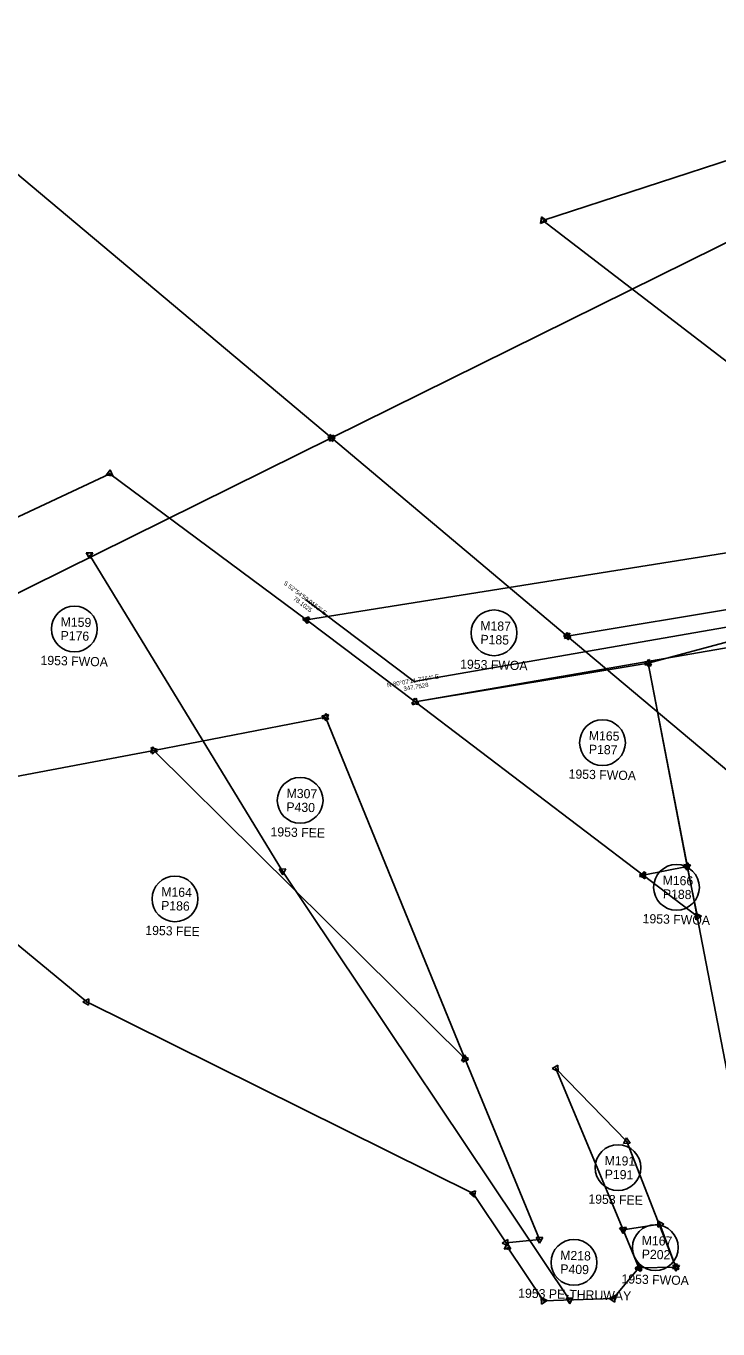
# Model space of a CAD drawing. Extents: x 325029 to 414988, y 1517527 to 1550420.
# Drawn here: x 363499 to 363896, y 1523755 to 1524502 of the extents above; entities that cross this region are included whole.
import ezdxf

# ---------------------------------------------------------------- set-up
doc = ezdxf.new("R2010")
doc.units = 0
for name, color, linetype in [('ADEFAULT', 7, 'Continuous'), ('Level 56', 7, 'Continuous'), ('MEE', 7, 'Continuous'), ('MHB', 7, 'Continuous'), ('MHBWOA', 7, 'Continuous'), ('MRBL1', 7, 'Continuous'), ('MRBL2', 7, 'Continuous'), ('XDEFAULT_P', 7, 'Continuous'), ('XDEFAULT_P_T', 7, 'Continuous')]:
    doc.layers.add(name, color=color, linetype=linetype)

msp = doc.modelspace()

# ---------------------------------------------------------------- linework, layer by layer
at = {"layer": 'ADEFAULT'}
for points in [[(363658.02, 1524161.47), (363661.51, 1524162.93)], [(363661.04, 1524159.19), (363658.02, 1524161.47)], [(363658.15, 1524161.98), (363661.89, 1524162.58)], [(363660.53, 1524159.05), (363658.15, 1524161.98)], [(363661.89, 1524162.58), (363660.53, 1524159.05)], [(363661.51, 1524162.93), (363661.04, 1524159.19)], [(363720.39, 1524113.46), (363722.99, 1524116.19)], [(363722.99, 1524116.19), (363724.06, 1524112.57)], [(363724.06, 1524112.57), (363720.39, 1524113.46)], [(363571.99, 1524084.21), (363571.14, 1524087.89)], [(363571.14, 1524087.89), (363574.75, 1524086.79)], [(363574.75, 1524086.79), (363571.99, 1524084.21)], [(363532.04, 1523942.18), (363535.4, 1523943.9)], [(363535.4, 1523943.9), (363535.21, 1523940.13)], [(363535.21, 1523940.13), (363532.04, 1523942.18)], [(363749.07, 1523908.3), (363750.73, 1523911.69)], [(363752.84, 1523908.55), (363749.07, 1523908.3)], [(363750.73, 1523911.69), (363752.84, 1523908.55)], [(363753.56, 1523832.56), (363757.14, 1523833.77)], [(363756.39, 1523830.07), (363753.56, 1523832.56)], [(363757.14, 1523833.77), (363756.39, 1523830.07)], [(363772.42, 1523803.69), (363775.52, 1523805.84)], [(363775.84, 1523802.08), (363772.42, 1523803.69)], [(363775.52, 1523805.84), (363775.84, 1523802.08)], [(363793.7, 1523803.66), (363791.86, 1523806.96)], [(363791.86, 1523806.96), (363795.64, 1523806.9)], [(363795.64, 1523806.9), (363793.7, 1523803.66)]]:
    msp.add_lwpolyline(points, dxfattribs=at)
for centre, radius in [((363660.19, 1524161.2), 1.09), ((363660.19, 1524161.2), 1.09), ((363722.48, 1524114.08), 0.227), ((363572.62, 1524086.3), 0.227), ((363534.22, 1523942.07), 0.227), ((363750.87, 1523909.51), 0.227), ((363755.7, 1523832.14), 0.227), ((363774.6, 1523803.87), 0.227), ((363793.73, 1523805.84), 0.227)]:
    msp.add_circle(centre, radius, dxfattribs=at)
at = {"layer": 'Level 56'}
for centre in [(363527.12, 1524155.92), (363767.66, 1524153.73), (363829.82, 1524090.72), (363656.53, 1524057.64), (363872.25, 1524007.76), (363584.75, 1524001.12), (363838.73, 1523847.02), (363860.13, 1523801.16), (363813.48, 1523792.66)]:
    msp.add_circle(centre, 13.12, dxfattribs=at)
at = {"layer": 'MEE'}
for p, q in [((363795.93, 1523770.69), (363775.36, 1523801.44)), ((363850.71, 1523789.48), (363835.91, 1523771.88)), ((363835.91, 1523771.88), (363795.93, 1523770.69))]:
    msp.add_line(p, q, dxfattribs=at)
for points in [[(363773.55, 1523800.23), (363775.22, 1523803.62)], [(363775.22, 1523803.62), (363777.32, 1523800.48)], [(363777.32, 1523800.48), (363773.55, 1523800.23)], [(363848.66, 1523788.74), (363851.09, 1523791.63)], [(363852.38, 1523788.08), (363848.66, 1523788.74)], [(363851.09, 1523791.63), (363852.38, 1523788.08)], [(363794.93, 1523768.75), (363794.75, 1523772.52)], [(363794.75, 1523772.52), (363798.11, 1523770.79)], [(363833.74, 1523772.04), (363837.14, 1523773.68)], [(363836.86, 1523769.92), (363833.74, 1523772.04)], [(363837.14, 1523773.68), (363836.86, 1523769.92)], [(363798.11, 1523770.79), (363794.93, 1523768.75)]]:
    msp.add_lwpolyline(points, dxfattribs=at)
for centre, radius in [((363775.36, 1523801.44), 1.09), ((363850.71, 1523789.48), 1.09), ((363835.91, 1523771.88), 0.227), ((363795.93, 1523770.69), 0.227)]:
    msp.add_circle(centre, radius, dxfattribs=at)
at = {"layer": 'MHB'}
for p, q in [((363795.7, 1524390.2), (364079.15, 1524482.56)), ((363937.94, 1524280.97), (363795.7, 1524390.2)), ((363170.57, 1524068.42), (363547.37, 1524244.94)), ((363547.37, 1524244.94), (363660.19, 1524161.2)), ((363671.1, 1524105.36), (363572.62, 1524086.3)), ((363750.87, 1523909.51), (363671.1, 1524105.36)), ((363572.62, 1524086.3), (363399.47, 1524053.32)), ((363572.62, 1524086.3), (363750.87, 1523909.51)), ((363750.87, 1523909.51), (363572.62, 1524086.3)), ((363399.47, 1524053.32), (363534.22, 1523942.07)), ((363534.22, 1523942.07), (363755.7, 1523832.14)), ((363793.73, 1523805.84), (363750.87, 1523909.51)), ((363843.71, 1523861.98), (363803.17, 1523903.89)), ((363803.17, 1523903.89), (363841.71, 1523811.42)), ((363871.97, 1523789.91), (363843.71, 1523861.98)), ((363755.7, 1523832.14), (363774.6, 1523803.87)), ((363774.6, 1523803.87), (363793.73, 1523805.84))]:
    msp.add_line(p, q, dxfattribs=at)
for points in [[(363794.24, 1524388.58), (363795.03, 1524392.27)], [(363794.37, 1524388.48), (363794.87, 1524392.22)], [(363794.87, 1524392.22), (363797.86, 1524389.92)], [(363795.03, 1524392.27), (363797.84, 1524389.75)], [(363797.84, 1524389.75), (363794.24, 1524388.58)], [(363797.86, 1524389.92), (363794.37, 1524388.48)], [(363545.38, 1524244.04), (363547.59, 1524247.1)], [(363549.14, 1524243.66), (363545.38, 1524244.04)], [(363547.59, 1524247.1), (363549.14, 1524243.66)], [(363658.02, 1524161.45), (363661.49, 1524162.95)], [(363661.06, 1524159.19), (363658.02, 1524161.45)], [(363661.49, 1524162.95), (363661.06, 1524159.19)], [(363669.04, 1524106.07), (363672.75, 1524106.79)], [(363671.51, 1524103.22), (363669.04, 1524106.07)], [(363669.08, 1524104.54), (363671.4, 1524107.52)], [(363672.82, 1524104.02), (363669.08, 1524104.54)], [(363671.4, 1524107.52), (363672.82, 1524104.02)], [(363672.75, 1524106.79), (363671.51, 1524103.22)], [(363571.03, 1524084.81), (363572.13, 1524088.42)], [(363574.71, 1524085.66), (363571.03, 1524084.81)], [(363572.13, 1524088.42), (363574.71, 1524085.66)], [(363749.91, 1523907.55), (363749.67, 1523911.32)], [(363749.67, 1523911.32), (363753.05, 1523909.65)], [(363753.05, 1523909.65), (363749.91, 1523907.55)], [(363800.99, 1523903.77), (363804.15, 1523905.84)], [(363804.37, 1523902.07), (363800.99, 1523903.77)], [(363804.15, 1523905.84), (363804.37, 1523902.07)], [(363841.88, 1523860.8), (363843.61, 1523864.16)], [(363843.61, 1523864.16), (363845.65, 1523860.98)], [(363845.65, 1523860.98), (363841.88, 1523860.8)], [(363839.98, 1523812.74), (363843.72, 1523812.25)], [(363841.43, 1523809.25), (363839.98, 1523812.74)], [(363843.72, 1523812.25), (363841.43, 1523809.25)], [(363869.94, 1523789.11), (363872.3, 1523792.07)], [(363873.68, 1523788.55), (363869.94, 1523789.11)], [(363872.3, 1523792.07), (363873.68, 1523788.55)]]:
    msp.add_lwpolyline(points, dxfattribs=at)
for centre, radius in [((363795.7, 1524390.21), 1.09), ((363795.7, 1524390.2), 1.09), ((363547.37, 1524244.94), 0.227), ((363660.19, 1524161.2), 1.09), ((363671.1, 1524105.36), 1.09), ((363671.1, 1524105.36), 1.09), ((363572.62, 1524086.3), 0.227), ((363750.87, 1523909.51), 0.227), ((363803.17, 1523903.89), 0.227), ((363843.71, 1523861.98), 0.227), ((363841.71, 1523811.41), 1.09), ((363871.97, 1523789.91), 1.09)]:
    msp.add_circle(centre, radius, dxfattribs=at)
at = {"layer": 'MHBWOA'}
for p, q in [((364011.63, 1524217.23), (363660.19, 1524161.2)), ((363722.48, 1524114.08), (364065.1, 1524173.61)), ((363660.19, 1524161.2), (363722.48, 1524114.08)), ((363904.35, 1524149.4), (363856.11, 1524136.32)), ((363856.11, 1524136.32), (363722.48, 1524114.08)), ((363878.3, 1524019.71), (363856.11, 1524136.32)), ((363856.11, 1524136.32), (363922.05, 1523793.54)), ((363722.48, 1524114.08), (363853.18, 1524014.69)), ((363853.18, 1524014.69), (363878.3, 1524019.71)), ((363884.32, 1523991.13), (363878.3, 1524019.71)), ((363853.18, 1524014.69), (363884.32, 1523991.13)), ((363862.72, 1523814.66), (363841.71, 1523811.42)), ((363841.71, 1523811.42), (363850.71, 1523789.48)), ((363871.97, 1523789.91), (363862.72, 1523814.66)), ((363850.71, 1523789.48), (363871.97, 1523789.91))]:
    msp.add_line(p, q, dxfattribs=at)
for points in [[(363853.98, 1524135.91), (363856.84, 1524138.38)], [(363854.19, 1524135.29), (363856.19, 1524138.5)], [(363856.19, 1524138.5), (363857.96, 1524135.16)], [(363856.84, 1524138.38), (363857.54, 1524134.66)], [(363857.54, 1524134.66), (363853.98, 1524135.91)], [(363854.07, 1524137.09), (363857.8, 1524137.71)], [(363856.47, 1524134.17), (363854.07, 1524137.09)], [(363857.96, 1524135.16), (363854.19, 1524135.29)], [(363857.8, 1524137.71), (363856.47, 1524134.17)], [(363720.96, 1524112.51), (363721.87, 1524116.17)], [(363721.87, 1524116.17), (363724.59, 1524113.55)], [(363724.59, 1524113.55), (363720.96, 1524112.51)], [(363876.16, 1524019.26), (363878.98, 1524021.78)], [(363879.76, 1524018.09), (363876.16, 1524019.26)], [(363878.15, 1524017.53), (363876.49, 1524020.93)], [(363876.49, 1524020.93), (363880.26, 1524020.67)], [(363880.26, 1524020.67), (363878.15, 1524017.53)], [(363878.98, 1524021.78), (363879.76, 1524018.09)], [(363851.01, 1524014.96), (363854.49, 1524016.43)], [(363854.03, 1524012.68), (363851.01, 1524014.96)], [(363851.09, 1524014.05), (363853.67, 1524016.81)], [(363854.77, 1524013.2), (363851.09, 1524014.05)], [(363853.67, 1524016.81), (363854.77, 1524013.2)], [(363854.49, 1524016.43), (363854.03, 1524012.68)], [(363883.31, 1523989.2), (363883.16, 1523992.97)], [(363883.16, 1523992.97), (363886.5, 1523991.22)], [(363886.5, 1523991.22), (363883.31, 1523989.2)], [(363861.62, 1523812.78), (363861.65, 1523816.56)], [(363861.65, 1523816.56), (363864.91, 1523814.65)], [(363839.68, 1523812.21), (363843.41, 1523812.78)], [(363842.04, 1523809.26), (363839.68, 1523812.21)], [(363839.98, 1523812.75), (363843.73, 1523812.24)], [(363841.42, 1523809.25), (363839.98, 1523812.75)], [(363843.73, 1523812.24), (363841.42, 1523809.25)], [(363843.41, 1523812.78), (363842.04, 1523809.26)], [(363864.91, 1523814.65), (363861.62, 1523812.78)], [(363848.53, 1523789.61), (363851.91, 1523791.3)], [(363851.69, 1523787.53), (363848.53, 1523789.61)], [(363851.91, 1523791.3), (363851.69, 1523787.53)], [(363871.81, 1523787.73), (363870.17, 1523791.13)], [(363870.17, 1523791.13), (363873.93, 1523790.86)], [(363873.93, 1523790.86), (363871.81, 1523787.73)]]:
    msp.add_lwpolyline(points, dxfattribs=at)
for centre, radius in [((363856.11, 1524136.32), 1.09), ((363856.11, 1524136.32), 1.09), ((363856.11, 1524136.32), 0.227), ((363722.48, 1524114.08), 0.227), ((363878.3, 1524019.71), 1.09), ((363878.3, 1524019.71), 0.227), ((363853.18, 1524014.69), 1.09), ((363853.18, 1524014.69), 0.227), ((363884.32, 1523991.13), 0.227), ((363841.71, 1523811.42), 1.09), ((363841.71, 1523811.41), 1.09), ((363862.72, 1523814.66), 0.227), ((363850.71, 1523789.48), 0.227), ((363871.97, 1523789.91), 0.227)]:
    msp.add_circle(centre, radius, dxfattribs=at)
at = {"layer": 'MRBL1'}
for p, q in [((363674.46, 1524265.46), (364151.59, 1524501.69)), ((362781.65, 1523823.41), (363674.46, 1524265.46)), ((363809.67, 1524151.83), (364211.09, 1524218.89)), ((363535.79, 1524198.54), (363646.44, 1524017.11)), ((363646.44, 1524017.11), (363810.93, 1523771.13))]:
    msp.add_line(p, q, dxfattribs=at)
for points in [[(363673.26, 1524263.64), (363673.5, 1524267.41)], [(363676.64, 1524265.32), (363673.26, 1524263.64)], [(363673.5, 1524267.41), (363676.64, 1524265.32)], [(363533.88, 1524199.58), (363537.65, 1524199.67)], [(363535.84, 1524196.35), (363533.88, 1524199.58)], [(363537.65, 1524199.67), (363535.84, 1524196.35)], [(363807.99, 1524150.44), (363809.31, 1524153.98)], [(363809.31, 1524153.98), (363811.71, 1524151.07)], [(363811.71, 1524151.07), (363807.99, 1524150.44)], [(363644.5, 1524018.12), (363648.28, 1524018.29)], [(363648.28, 1524018.29), (363646.54, 1524014.93)], [(363646.54, 1524014.93), (363644.5, 1524018.12)], [(363808.97, 1523772.09), (363812.74, 1523772.34)], [(363811.07, 1523768.95), (363808.97, 1523772.09)], [(363812.74, 1523772.34), (363811.07, 1523768.95)]]:
    msp.add_lwpolyline(points, dxfattribs=at)
for centre, radius in [((363674.46, 1524265.46), 0.227), ((363535.8, 1524198.53), 1.09), ((363809.67, 1524151.83), 1.09), ((363646.44, 1524017.11), 0.227), ((363810.93, 1523771.13), 1.09)]:
    msp.add_circle(centre, radius, dxfattribs=at)
at = {"layer": 'MRBL2'}
for p, q in [((363396.75, 1524498.84), (363674.46, 1524265.46)), ((363674.46, 1524265.46), (363809.67, 1524151.83)), ((363809.67, 1524151.83), (364282.48, 1523754.5))]:
    msp.add_line(p, q, dxfattribs=at)
for points in [[(363672.31, 1524265.84), (363675.86, 1524267.12)], [(363675.21, 1524263.4), (363672.31, 1524265.84)], [(363675.86, 1524267.12), (363675.21, 1524263.4)], [(363807.52, 1524152.21), (363811.07, 1524153.5)], [(363811.07, 1524153.5), (363810.41, 1524149.78)], [(363810.41, 1524149.78), (363807.52, 1524152.21)]]:
    msp.add_lwpolyline(points, dxfattribs=at)
for centre in [(363674.46, 1524265.46), (363809.67, 1524151.83)]:
    msp.add_circle(centre, 0.227, dxfattribs=at)
at = {"layer": 'XDEFAULT_P'}
for p, q in [((363721.83, 1524125.76), (364064.43, 1524185.43)), ((363659.53, 1524172.86), (363721.83, 1524125.76))]:
    msp.add_line(p, q, dxfattribs=at)

# ---------------------------------------------------------------- texts
at = {"layer": 'Level 56'}
for s, height, p in [('M159', 5.249, (363519.19, 1524157.44)), ('M187', 5.249, (363759.73, 1524155.25)), ('P176', 5.249, (363519.15, 1524149.57)), ('P185', 5.249, (363759.82, 1524147.37)), ('1953 FWOA', 5.249, (363507.66, 1524135.41)), ('1953 FWOA', 5.249, (363748.2, 1524133.22)), ('M165', 5.249, (363821.95, 1524092.24)), ('P187', 5.249, (363821.98, 1524084.36)), ('1953 FWOA', 5.249, (363810.37, 1524070.21)), ('M307', 5.249, (363648.69, 1524059.16)), ('P430', 5.249, (363648.58, 1524051.29)), ('1953 FEE', 5.249, (363639.5, 1524037.07)), ('M166', 5.249, (363864.25, 1524009.28)), ('M164', 5.249, (363576.87, 1524002.64)), ('P188', 5.249, (363864.41, 1524001.4)), ('P186', 5.249, (363576.79, 1523994.76)), ('1953 FWOA', 5.249, (363852.79, 1523987.25)), ('1953 FEE', 5.249, (363567.72, 1523980.55)), ('M191', 5.249, (363830.98, 1523848.54)), ('P191', 5.249, (363831.06, 1523840.66)), ('1953 FEE', 5.249, (363821.7, 1523826.45)), ('M167', 5.249, (363852.26, 1523802.68)), ('M218', 5.249, (363805.55, 1523794.19)), ('P202', 5.249, (363852.29, 1523794.8)), ('P409', 5.249, (363805.62, 1523786.31)), ('1953 FWOA', 5.249, (363840.68, 1523780.65)), ('1953 PE-THRUWAY', 5.2493, (363781.47, 1523772.49))]:
    msp.add_text(s, height=height, rotation=358.49067, dxfattribs=at).set_placement(p)
at = {"layer": 'XDEFAULT_P_T'}
for s, height, rotation, p in [('S 52%%d54\'59.9152" E', 2.5008, 322.91664, (363646.72, 1524181.76)), ('78.1025', 2.501, 322.91664, (363652.31, 1524172.83)), ('N 80%%d07\'11.7764" E', 2.5008, 9.88006, (363706.58, 1524122.47)), ('347.7528', 2.501, 9.88006, (363716.05, 1524120.31))]:
    msp.add_text(s, height=height, rotation=rotation, dxfattribs=at).set_placement(p)

doc.saveas('drawing.dxf')
